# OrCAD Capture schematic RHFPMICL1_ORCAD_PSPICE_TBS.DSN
size Custom
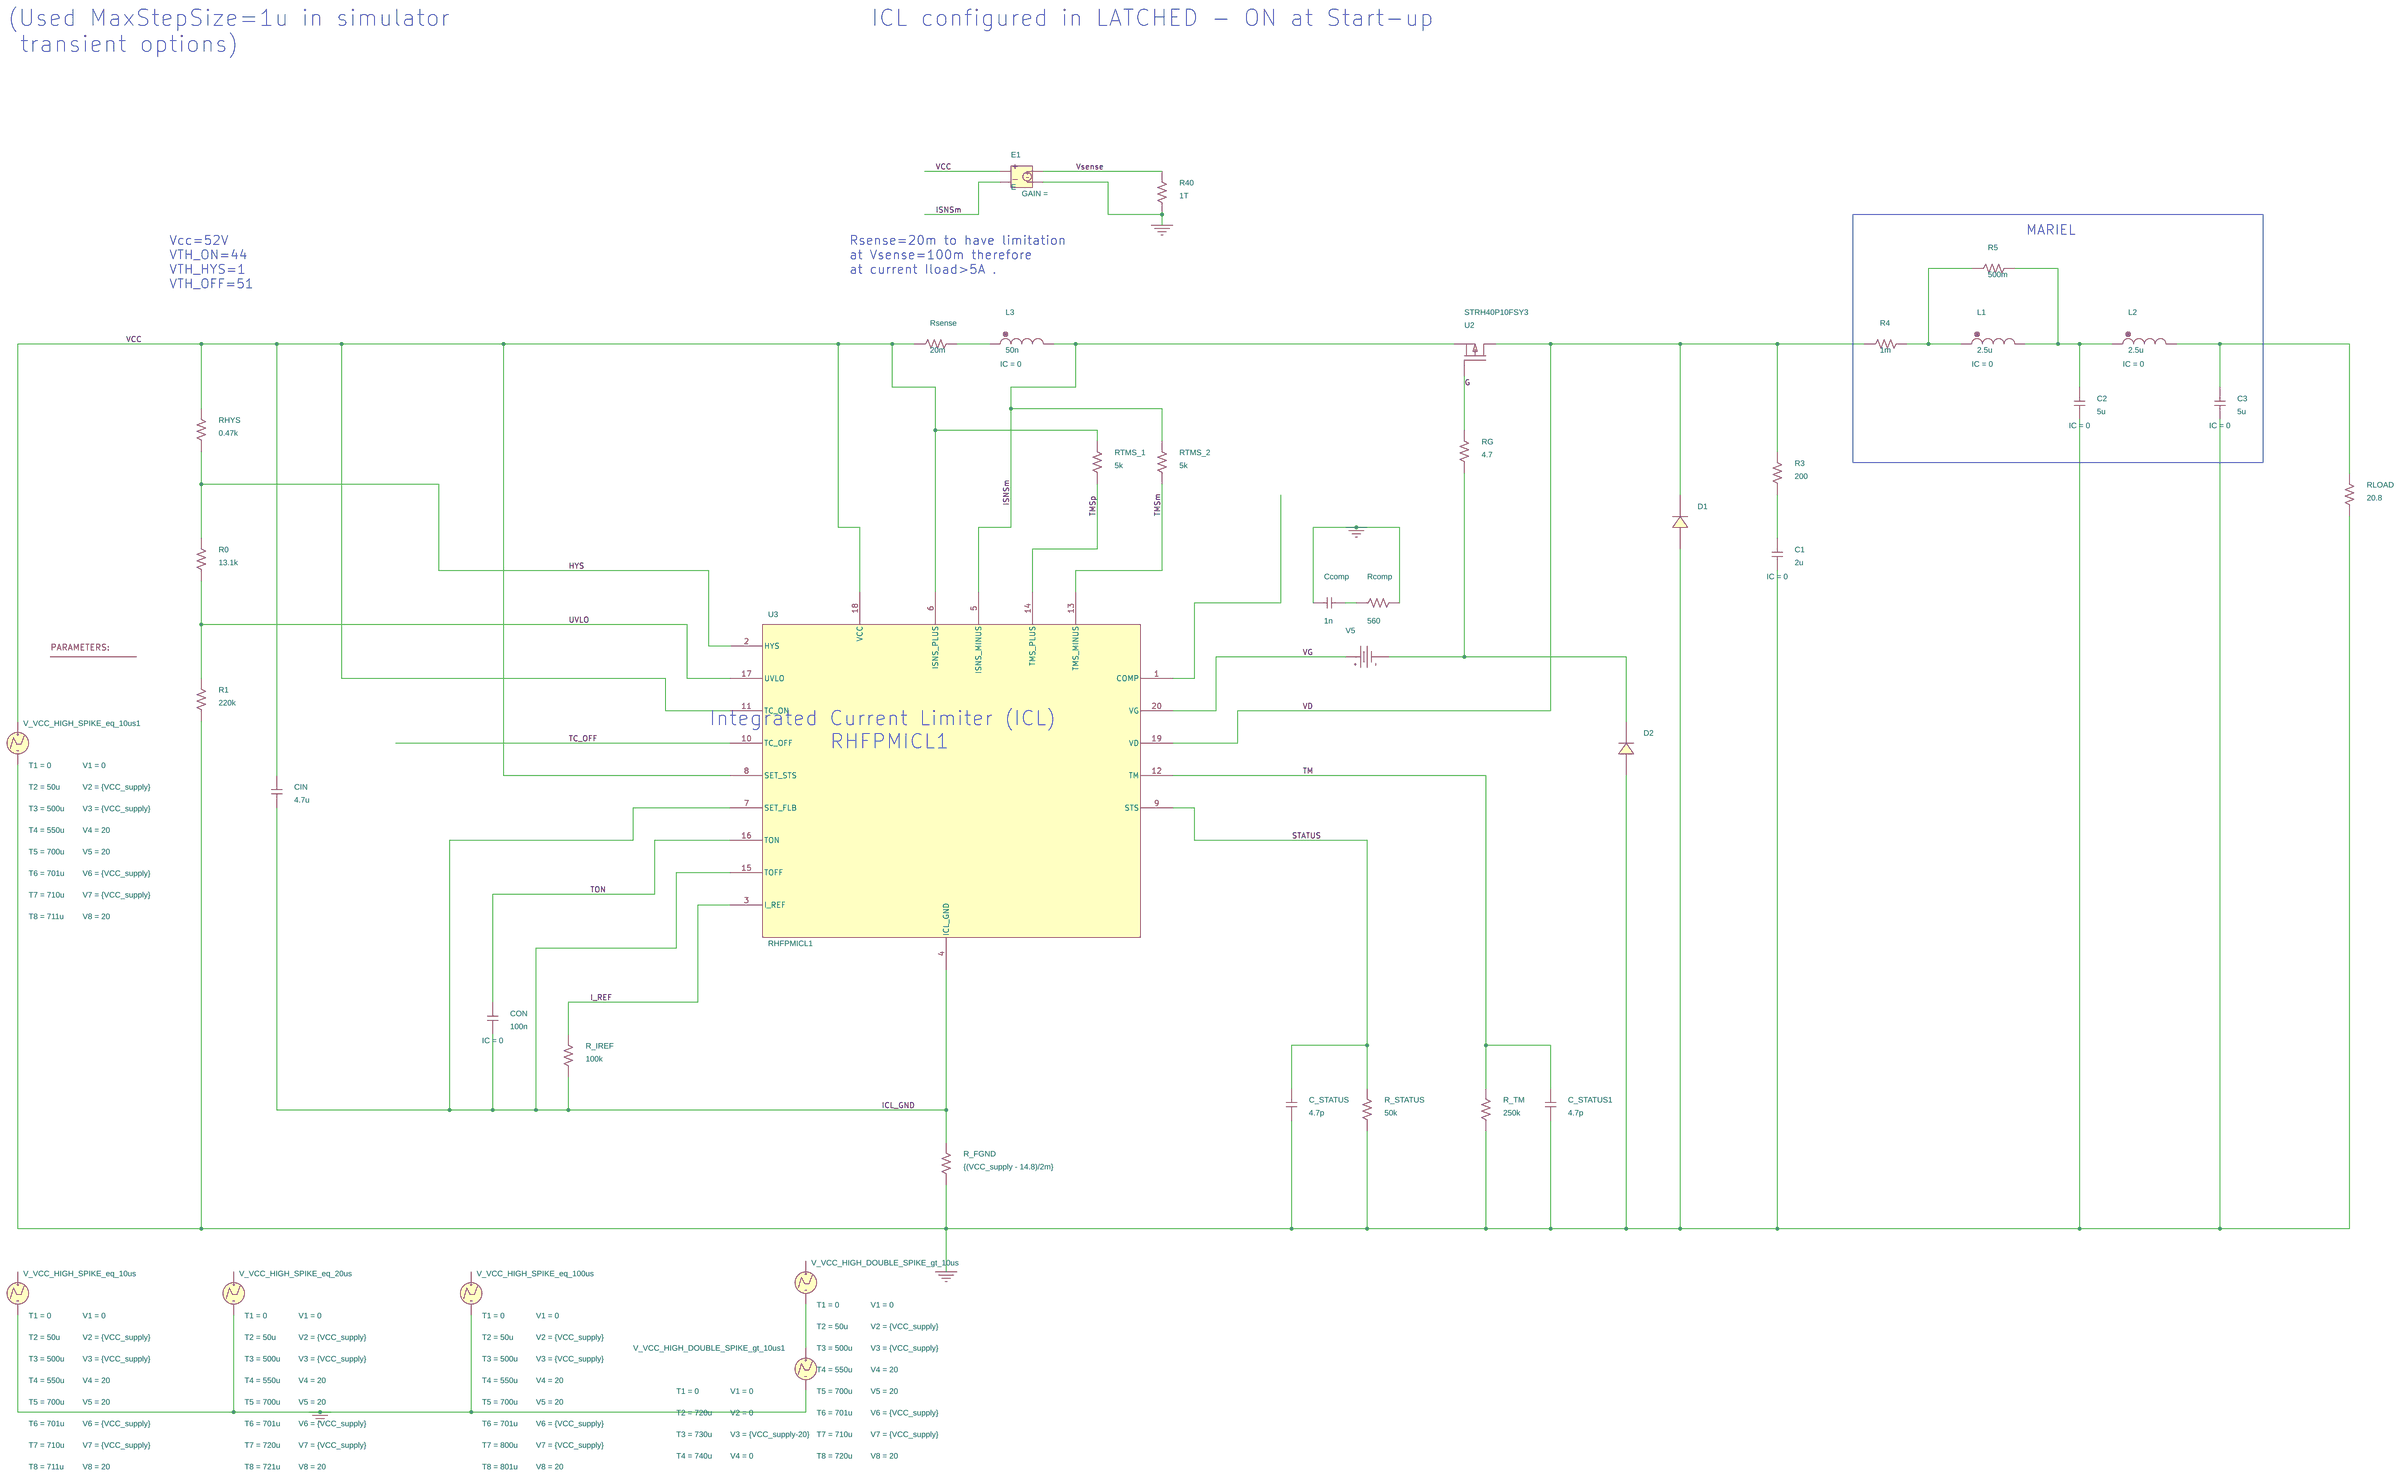
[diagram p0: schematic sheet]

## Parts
1  PARAM
C1  2u  [RAD/CK05]
C2  5u  [RAD/CK05]
C3  5u  [RAD/CK05]
C_STATUS  4.7p  [RAD/CK05]
C_STATUS1  4.7p  [RAD/CK05]
Ccomp  1n  [RAD/CK05]
CIN  4.7u  [RAD/CK05]
CON  100n  [RAD/CK05]
D1  STTH310S  [DO41]
D2  STTH310S  [DO41]
E1  E
L1  2.5u  [DISC/.350x.175/LS.200x.100/.034]
L2  2.5u  [DISC/.350x.175/LS.200x.100/.034]
L3  50n  [DISC/.350x.175/LS.200x.100/.034]
R0  13.1k  [AX/RC05]
R1  220k  [AX/RC05]
R3  200  [AX/RC05]
R4  1m  [AX/RC05]
R5  500m  [AX/RC05]
R40  1T  [AX/RC05]
R_FGND  {(VCC_supply - 14.8)/2m}  [AX/RC05]
R_IREF  100k  [AX/RC05]
R_STATUS  50k  [AX/RC05]
R_TM  250k  [AX/RC05]
Rcomp  560  [AX/RC05]
RG  4.7  [AX/RC05]
RHYS  0.47k  [AX/RC05]
RLOAD  20.8  [AX/RC05]
Rsense  20m  [AX/RC05]
RTMS_1  5k  [AX/RC05]
RTMS_2  5k  [AX/RC05]
U2  STRH40P10FSY3
U3  RHFPMICL1
V5  VDC
V_VCC_HIGH_DOUBLE_SPIKE_gt_10us  VPWL
V_VCC_HIGH_DOUBLE_SPIKE_gt_10us1  VPWL
V_VCC_HIGH_SPIKE_eq_10us  VPWL
V_VCC_HIGH_SPIKE_eq_10us1  VPWL
V_VCC_HIGH_SPIKE_eq_20us  VPWL
V_VCC_HIGH_SPIKE_eq_100us  VPWL

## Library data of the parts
1 = PARAM: VCC_supply: 52
C1-C3 CON = C: IC: 0
C_STATUS C_STATUS1 Ccomp CIN = C
D1 D2 = STTH310S
E1 = E
L1-L3 = L: IC: 0
R0 R1 R3-R5 R40 R_FGND R_IREF R_STATUS R_TM Rcomp RG RHYS RLOAD Rsense RTMS_1 RTMS_2 = R
U2 = STRH40P10FSY3
U3 = RHFPMICL1
V5 = VDC
V_VCC_HIGH_DOUBLE_SPIKE_gt_10us = VPWL: T1: 0; T2: 50u; T3: 500u; T4: 550u; T5: 700u; T6: 701u; T7: 710u; T8: 720u; V1: 0; V2: {VCC_supply}; V3: {VCC_supply}; V4: 20; V5: 20; V6: {VCC_supply}; V7: {VCC_supply}; V8: 20
V_VCC_HIGH_DOUBLE_SPIKE_gt_10us1 = VPWL: T1: 0; T2: 720u; T3: 730u; T4: 740u; V1: 0; V2: 0; V3: {VCC_supply-20}; V4: 0
V_VCC_HIGH_SPIKE_eq_10us V_VCC_HIGH_SPIKE_eq_10us1 = VPWL: T1: 0; T2: 50u; T3: 500u; T4: 550u; T5: 700u; T6: 701u; T7: 710u; T8: 711u; V1: 0; V2: {VCC_supply}; V3: {VCC_supply}; V4: 20; V5: 20; V6: {VCC_supply}; V7: {VCC_supply}; V8: 20
V_VCC_HIGH_SPIKE_eq_20us = VPWL: T1: 0; T2: 50u; T3: 500u; T4: 550u; T5: 700u; T6: 701u; T7: 720u; T8: 721u; V1: 0; V2: {VCC_supply}; V3: {VCC_supply}; V4: 20; V5: 20; V6: {VCC_supply}; V7: {VCC_supply}; V8: 20
V_VCC_HIGH_SPIKE_eq_100us = VPWL: T1: 0; T2: 50u; T3: 500u; T4: 550u; T5: 700u; T6: 701u; T7: 800u; T8: 801u; V1: 0; V2: {VCC_supply}; V3: {VCC_supply}; V4: 20; V5: 20; V6: {VCC_supply}; V7: {VCC_supply}; V8: 20

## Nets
VCC: CIN.2 E1.1 RHYS.2 Rsense.1 RTMS_1.2 U3.6(ISNS_PLUS) U3.8(SET_STS) U3.11(TC_ON) U3.18(VCC) V_VCC_HIGH_SPIKE_eq_10us1.1(+)
0: C1.1 C2.1 C3.1 C_STATUS.1 C_STATUS1.1 Ccomp.1 D1.2(A) D2.2(A) E1.4 R1.1 R40.1 R_FGND.1 R_STATUS.1 R_TM.1 Rcomp.2 RLOAD.1 V_VCC_HIGH_DOUBLE_SPIKE_gt_10us1.2(-) V_VCC_HIGH_SPIKE_eq_10us.2(-) V_VCC_HIGH_SPIKE_eq_10us1.2(-) V_VCC_HIGH_SPIKE_eq_20us.2(-) V_VCC_HIGH_SPIKE_eq_100us.2(-)
G: RG.2 U2.2(G)
HYS: R0.2 RHYS.1 U3.2(HYS)
I_REF: R_IREF.2 U3.3(I_REF)
ICL_GND: CIN.1 CON.1 R_FGND.2 R_IREF.1 U3.4(ICL_GND) U3.7(SET_FLB) U3.15(TOFF)
ISNSm: E1.2 L3.2 RTMS_2.2 U2.3(S) U3.5(ISNS_MINUS)
STATUS: C_STATUS.2 R_STATUS.2 U3.9(STS)
TC_OFF: U3.10(TC_OFF)
TM: C_STATUS1.2 R_TM.2 U3.12(TM)
TMSm: RTMS_2.1 U3.13(TMS_MINUS)
TMSp: RTMS_1.1 U3.14(TMS_PLUS)
TON: CON.2 U3.16(TON)
UVLO: R0.1 R1.2 U3.17(UVLO)
VD: D1.1(C) R3.2 R4.1 U2.1(D) U3.19(VD)
VG: U3.20(VG) V5.0(+)
Vsense: E1.3 R40.2
N16432529: L3.1 Rsense.2
N16432557: D2.1(C) RG.1 V5.1(-)
N16433611: C1.2 R3.1
N16433639: L1.1 R4.2 R5.1
N16433657: C2.2 L1.2 L2.1 R5.2
N16433691: C3.2 L2.2 RLOAD.2
N16442011: Ccomp.2 Rcomp.1
N16582949: V_VCC_HIGH_DOUBLE_SPIKE_gt_10us.2(-) V_VCC_HIGH_DOUBLE_SPIKE_gt_10us1.1(+)

Not connected (* = marked no-connect by the designer): U3 1(COMP); V_VCC_HIGH_DOUBLE_SPIKE_gt_10us 1(+); V_VCC_HIGH_SPIKE_eq_10us 1(+); V_VCC_HIGH_SPIKE_eq_20us 1(+); V_VCC_HIGH_SPIKE_eq_100us 1(+)

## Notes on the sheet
- (Used MaxStepSize=1u in simulator
   transient options)
- ICL configured in LATCHED - ON at Start-up
- MARIEL
- Vcc=52V
  VTH_ON=44
  VTH_HYS=1
  VTH_OFF=51
- Rsense=20m to have limitation
  at Vsense=100m therefore
  at current Iload>5A .
- Integrated Current Limiter (ICL)
             RHFPMICL1
